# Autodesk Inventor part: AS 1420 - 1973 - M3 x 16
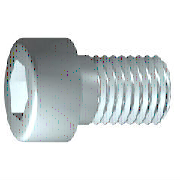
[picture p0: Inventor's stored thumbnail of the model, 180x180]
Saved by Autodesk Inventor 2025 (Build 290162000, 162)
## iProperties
Created: 2024-01
Part Number: AS 1420 - 1973 - M3 x 16
Material: Acciaio, Dolce
Description: Viti con esagono incassato metriche ISO
Document SubType Name: Modeling
Standard: AS 1420 - 1973
Designer: R5800u
Standards Organization: AS
Language: it-IT
Size Designation: M3 x 16
Categories: <MemberInstance><Categories><Category DisplayName="Elementi di fissaggio" InternalName="e4da775c-781d-43d5-af7c-5136215cf5a6" Mnemonic="FSTN"><Category DisplayN
Density: 7.85 g/cm^3
Appearance: Semilucidato
IsCustomPart: 0
Author: R5800u
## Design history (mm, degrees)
body "Solid1"
workplane "Work Plane1"
fillet "Fillet2" dims "d30" = 0.1 (= R)
revolve "Corpo" stored, may be unused: angle "d10" = 90 deg
sketch "Schizzo2"
  geometry: L1 (0, -3.85)-(0, 3.85) reference; L2 (-3.85, 0)-(3.85, 0) reference; L3 (1.443, 0)-(0.722, -1.25); L4 (0.722, -1.25)-(-0.722, -1.25); L5 (-0.722, -1.25)-(-1.443, 0); L6 (-1.443, 0)-(-0.722, 1.25); L7 (-0.722, 1.25)-(0.722, 1.25); L8 (0.722, 1.25)-(1.443, 0); 2 further points
  constraints: 12 end point, 1 coincident, 1 horizontal alignment, 1 point on line, 12 other
extrude "Intaglio" join sketch "Schizzo2" stored distance "d11" = 10; taper "d12" = 0 deg
fillet "Raccordo1" dims "d17" = 0.3 (= RR)
feature "Filettatura" dims "d13" = 12 (= GEL), "d14" = 0
chamfer "Smusso1" distance "d15" = 0.30673 (= -0.5 x SPD + 0.5 x GD); stored, may be unused: second distance "d16" = 0.30673 (= GUL), angle "d27" = 45 deg
sketch "Schizzo1"
  geometry: L1 (-0.867, 0)-(16, 0); L2 (16, 0)-(16, 1.5); L3 (16, 1.5)-(4, 1.5); L4 (4, 1.5)-(3.693, 1.5); L5 (3.693, 1.5)-(0, 1.5); L6 (0, 1.5)-(0, 2.75); L7 (0, 2.75)-(-3, 2.75); L8 (-3, 2.75)-(-3, 1.443); L9 (-3, 1.443)-(-1.7, 1.443); L10 (-1.7, 1.443)-(-0.867, 0); L11 (-6.8, 0)-(19.8, 0) reference; L12 (0, -0.55)-(0, 3.3) reference; L13 (4, 1.5)-(0, 1.5)
  constraints: 22 end point, 6 parallel, 2 collinear, 2 perpendicular, 1 horizontal, 1 point on line
  dimensions: "d1" = 12 distance from line of L3.end L2 (= GEL); "d2" = 0.30683 distance of L4.end L3.end (computed from GAL); "d3" = 3 distance between parallel lines of L8 L6 (= KOH); "d4" = 1.3 distance of L8.end L9.end (= INTI); "d5" = 60 deg angle of L10 L1; "d6" = 3 diameter of L3 L1 (= GD); "d7" = 3 diameter of L5 L1 (= BDM); "d8" = 2.88675 diameter of L9 L1 (= 1.1547 x SW); "d9" = 5.5 diameter of L7 L1 (= KOD); "d26" = 16 distance between parallel lines of L12 L2 (= NLG)
other parameters: "GD" = 3 (= NND) [user parameter; used in 2 equation terms], "NLG" = 16 [user parameter; used in 1 equation term], "GEL" = 12 [user parameter; used in 2 equation terms], "KOD" = 5.5 [user parameter; used in 1 equation term], "KOH" = 3 (= NND) [user parameter; used in 1 equation term], "INTI" = 1.3 [user parameter; used in 1 equation term], "GAL" = 0.30673 (= 0.61345 x PTC) [user parameter; used in 1 equation term], "GUL" = 0.30673 (= 0.61345 x PTC) [user parameter; used in 1 equation term], "BDM" = 3 (= NND) [user parameter; used in 1 equation term], "SW" = 2.5 [user parameter; used in 2 equation terms], "RR" = 0.3 (= 0.1 x NND) [user parameter; used in 1 equation term], "SPD" = 2.38655 (= NND - 1.2269 x PTC) [user parameter; used in 1 equation term], "d19" = 0, "d28" = 0, "d29" = 0, "R" = 0.1 [user parameter; used in 1 equation term], "PHH" = 0.13 [user parameter], "GD1" = 2.38655 (= THREADDIA - 1.2269 x PTC) [user parameter], "THREADDIA" = 3 [user parameter; used in 1 equation term], "FAWI" = 45 deg [user parameter], "PTC" = 0.5 [user parameter; used in 5 equation terms], "KOH1" = 2.7 [user parameter], "NND" = 3 [user parameter; used in 5 equation terms], "TOA" = 30 deg [user parameter], "E0" = 2.8875 (= 1.155 x SW) [user parameter]
